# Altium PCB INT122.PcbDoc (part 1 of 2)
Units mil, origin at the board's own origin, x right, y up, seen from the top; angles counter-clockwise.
Board outline 4500 x 3260 mil, 4 copper layers (Top Layer, GND Layer, VCC Layer, Bottom Layer), stack 61.6 mil thick; 94 components, 30 nets, 233 pads, 39 vias.
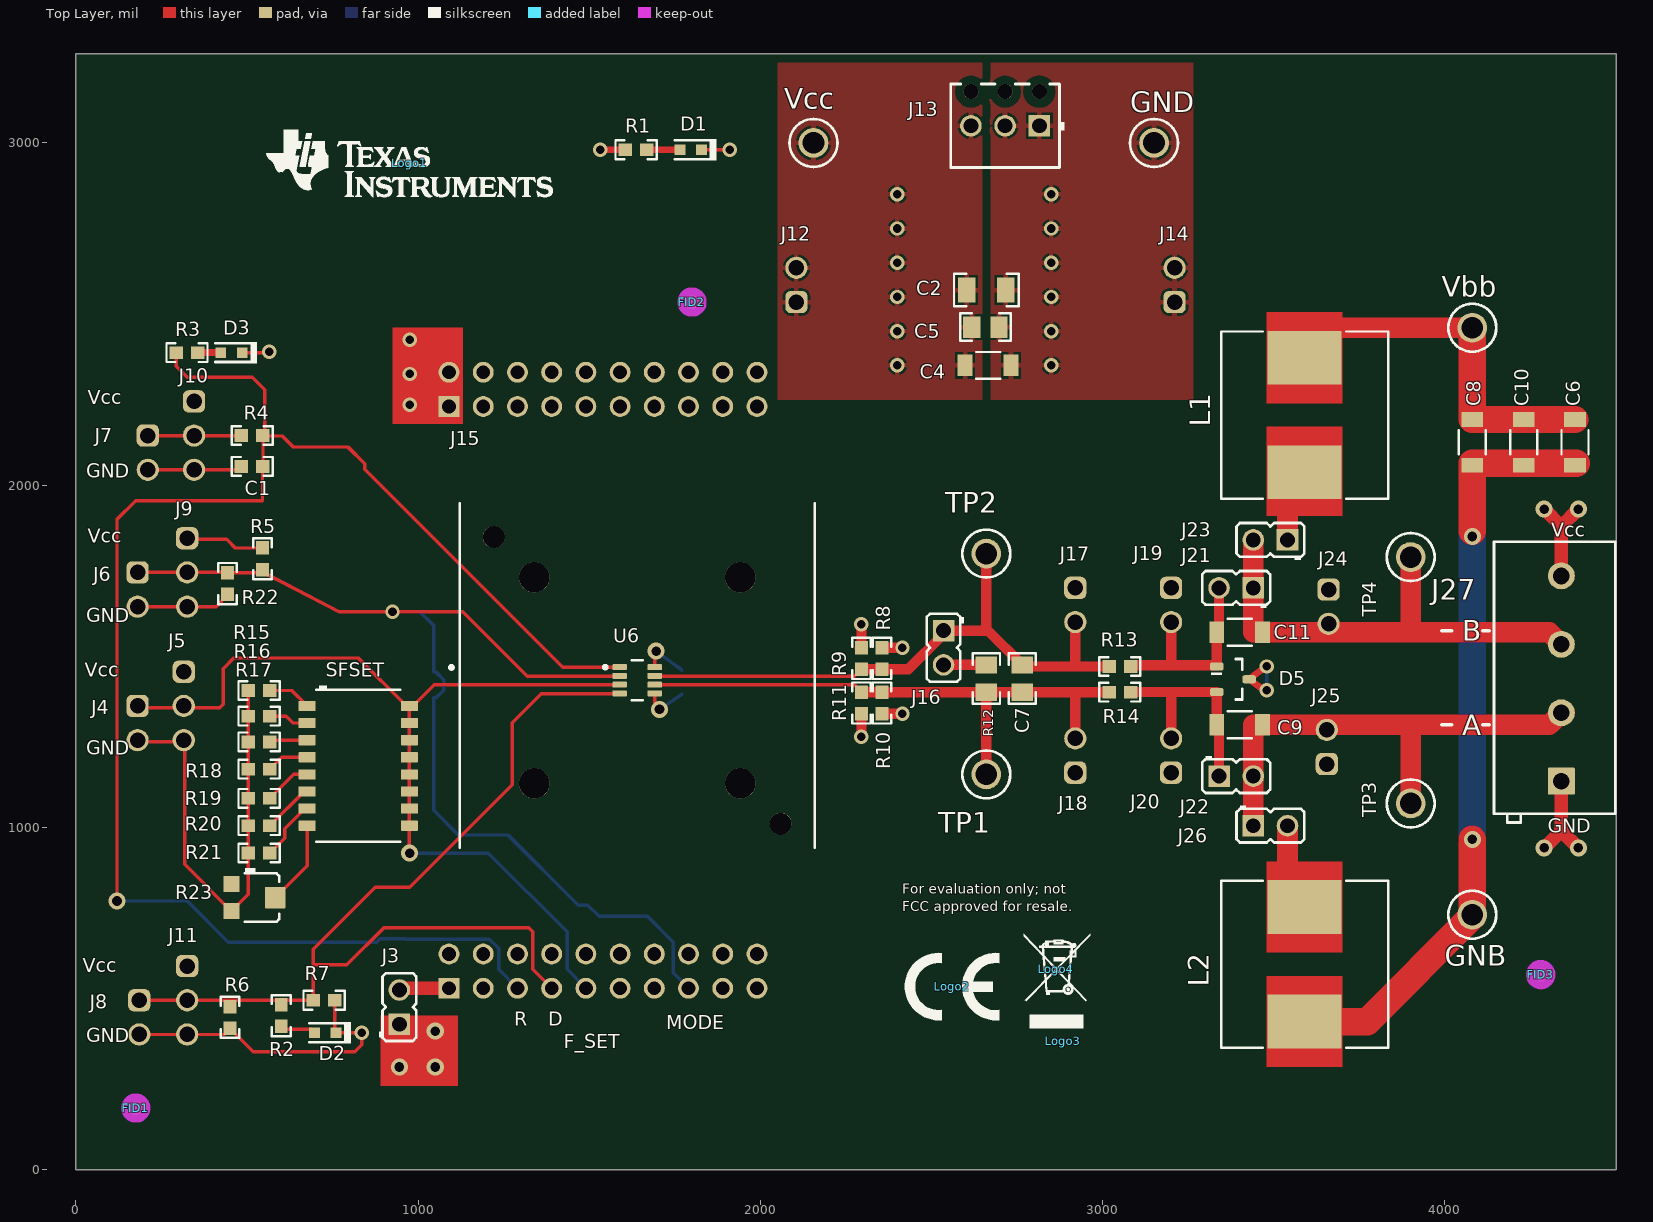
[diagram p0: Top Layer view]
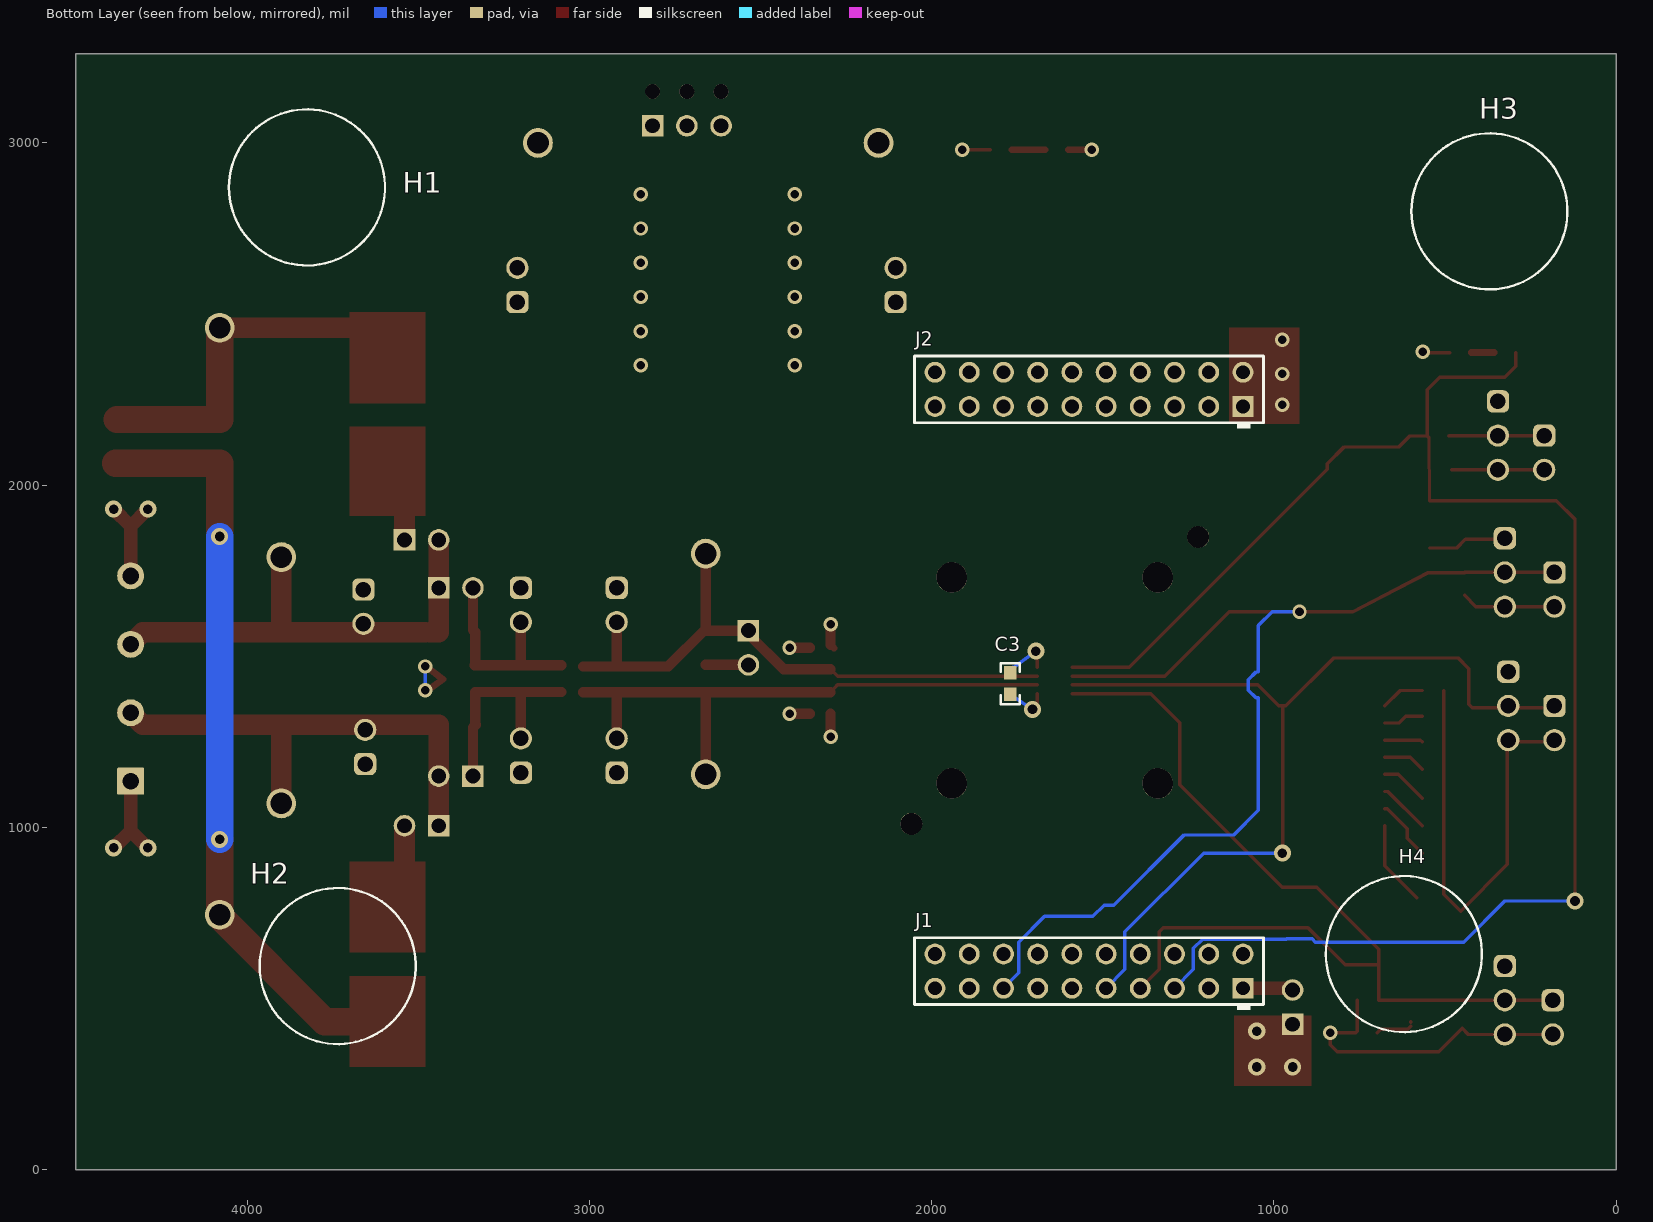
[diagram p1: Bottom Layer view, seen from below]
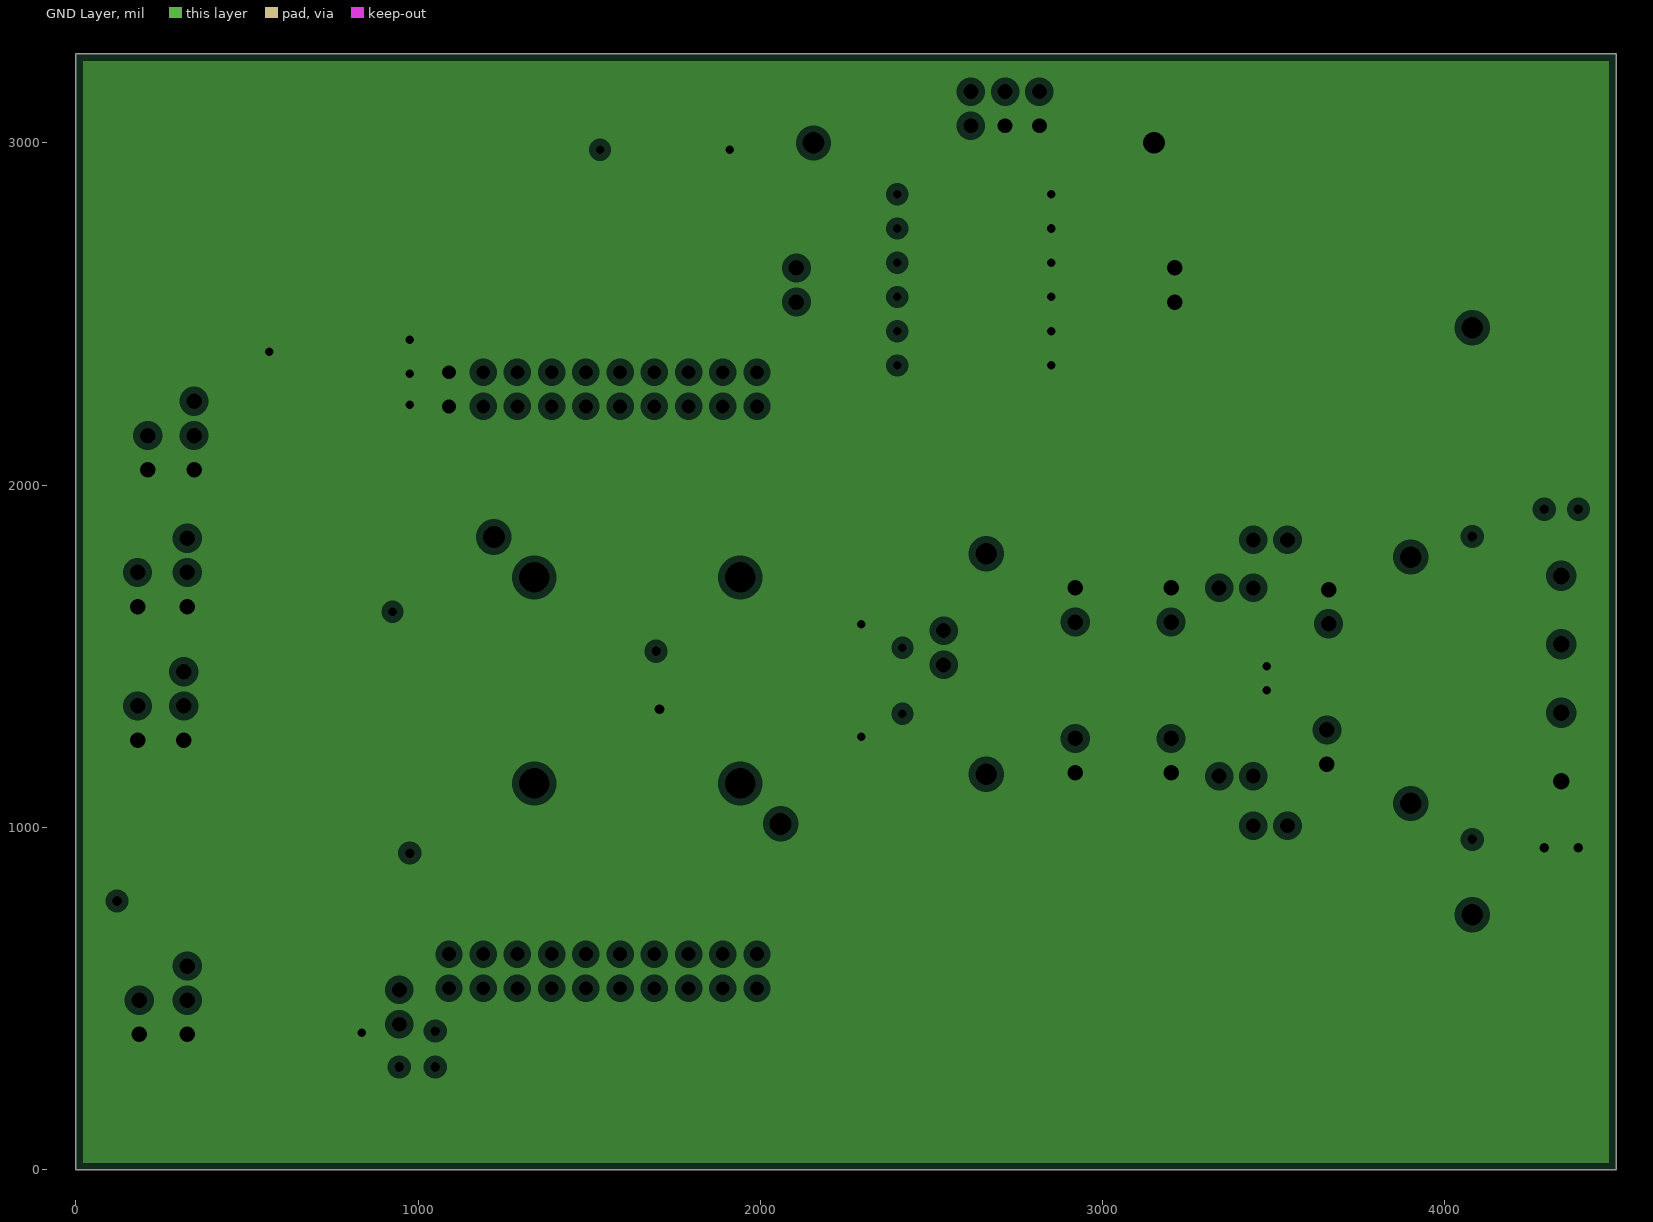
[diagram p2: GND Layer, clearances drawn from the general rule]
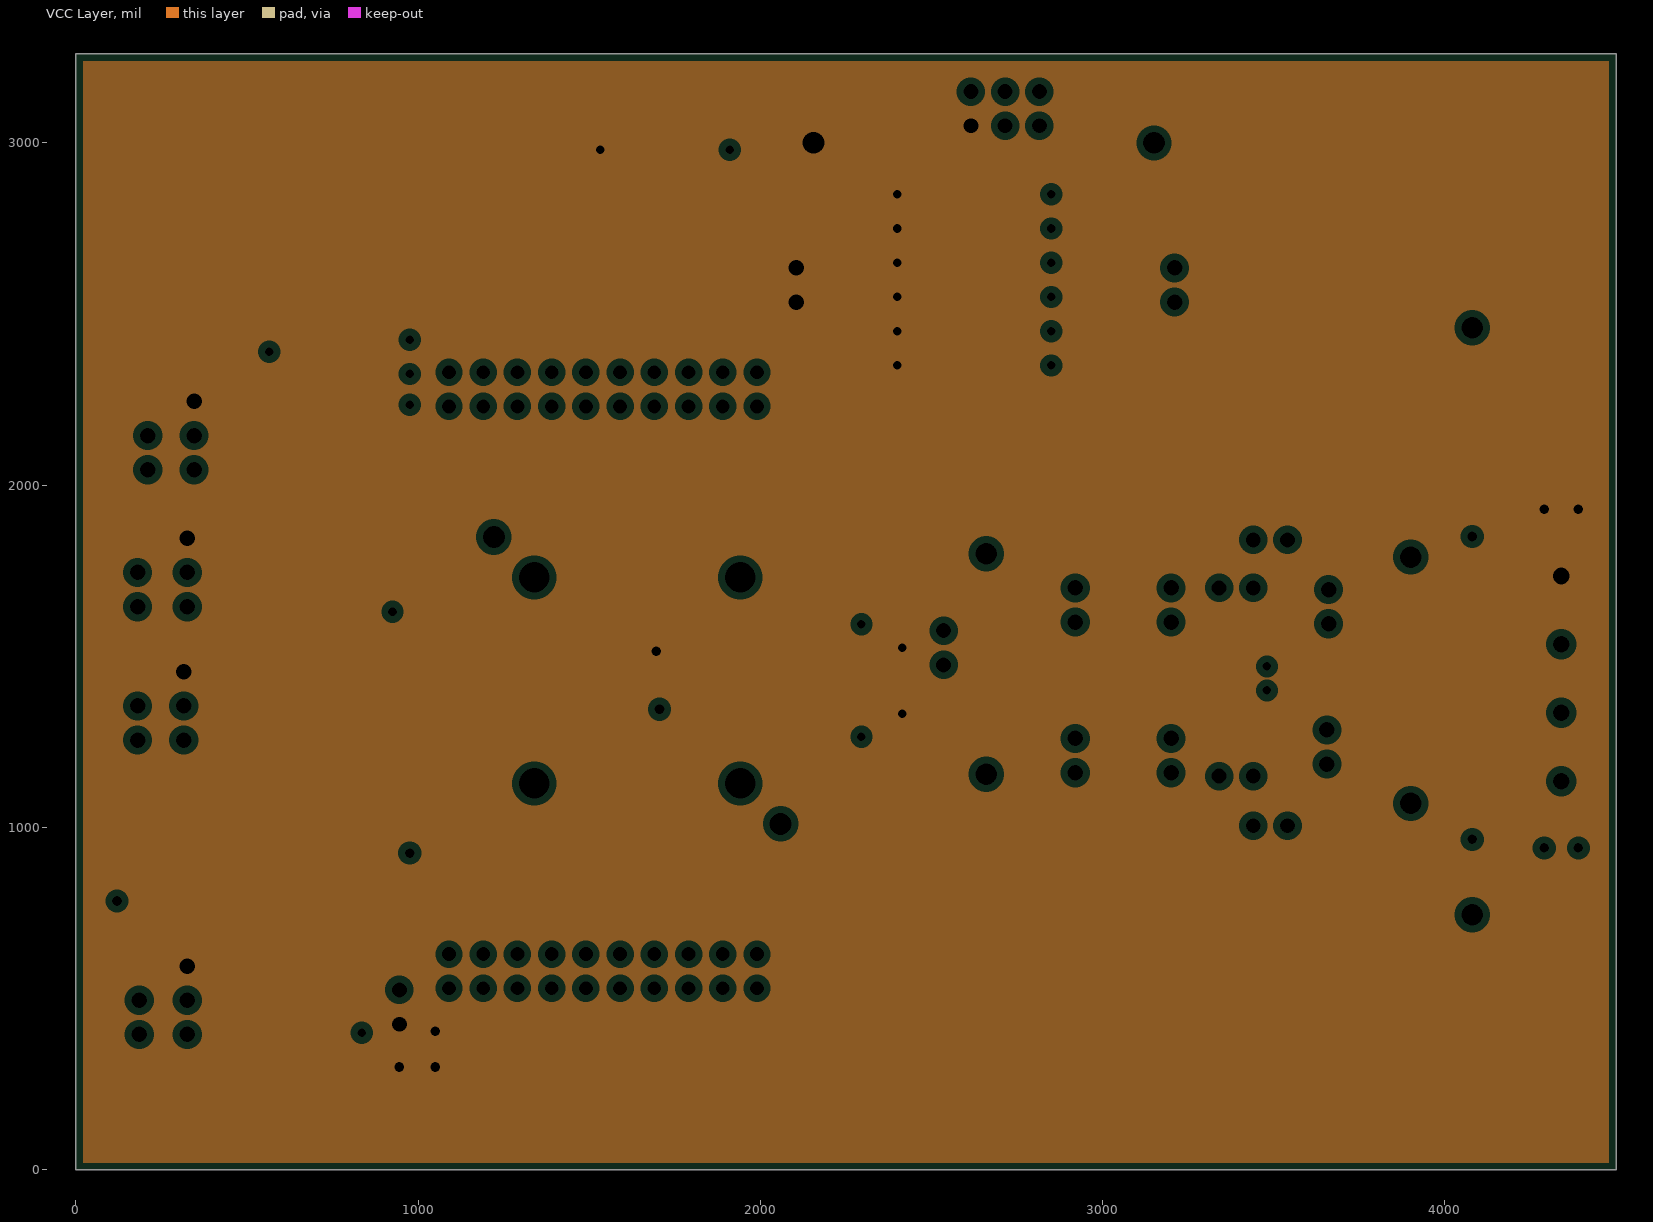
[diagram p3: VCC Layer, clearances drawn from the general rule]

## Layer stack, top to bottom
Top Solder: solder mask 0.4, Solder Resist, Dk 3.5
Top Layer: signal copper 1.4
Dielectric 1: prepreg 8, FR-4, Dk 4.2
GND Layer: plane copper 1.4, net GND_BRD
Dielectric 2: core 40, FR-4, Dk 4.2
VCC Layer: plane copper 1.4, net VCC_BRD
Dielectric 3: prepreg 8, FR-4, Dk 4.2
Bottom Layer: signal copper 1.4
Bottom Solder: solder mask 0.4, Solder Resist, Dk 3.5

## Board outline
0,0 4500,0 4500,3260 0,3260

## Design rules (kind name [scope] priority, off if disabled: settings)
AcuteAngle [All] p1: minimum=4.50000000000000E+0001 checktracksonly=FALSE
AssemblyTestPointUsage [All] p1: valid=2
BoardOutlineClearance BoardOutlineClearance_MountingHoles [OnCopper and InComponentClass('Mounting Holes')] p1: gap=40 ignorepadtopadclearanceinfootprint=FALSE
BoardOutlineClearance BoardOutlineClearance_Poly [OnCopper and IsPoly] p2: gap=25 ignorepadtopadclearanceinfootprint=FALSE
BoardOutlineClearance [OnCopper and Not InComponentClass('Logo') and not InComponentClass('FiducialMark') and not InRegion(1000,500,4000,800) and not InPoly] p3: gap=75 ignorepadtopadclearanceinfootprint=FALSE
Clearance Clearance_Keepouts [((IsTrack Or IsArc) And Not InPoly) And IsFree and IsKeepOut vs ((IsTrack Or IsArc) And Not InPoly) And IsFree and IsKeepOut] p1: gap=0 ignorepadtopadclearanceinfootprint=FALSE
Clearance Clearance_Poly [InPolygon] p2: gap=25 ignorepadtopadclearanceinfootprint=FALSE except(0: Arc-Hole Track-Hole SMDPad-Hole THPad-Hole Via-Hole Fill-Hole Poly-Hole Region-Hole Text-Hole)
Clearance Clearance_FiducialMark [IsKeepOut and InComponentClass('FiducialMark') vs IsPad and InComponentClass('FiducialMark')] p3: gap=0 ignorepadtopadclearanceinfootprint=FALSE
Clearance [All] p4: gap=7.87 ignorepadtopadclearanceinfootprint=FALSE except(0: Arc-Hole Track-Hole SMDPad-Hole THPad-Hole Via-Hole Fill-Hole Poly-Hole Region-Hole Text-Hole)
ComponentClearance ComponentClearance_THtoSMT_Socket [InComponent('JS') vs InComponent('U6')] p1: gap=0 collisioncheckmode=3 verticalgap=0 showdistances=FALSE
ComponentClearance ComponentClearance_L1_Multipad [InComponent('L1') vs InComponent('L1B')] p2: gap=-1 collisioncheckmode=3 verticalgap=100000 showdistances=FALSE
ComponentClearance ComponentClearance_L2_Multipad [InComponent('L2') vs InComponent('L2B')] p3: gap=-1 collisioncheckmode=3 verticalgap=100000 showdistances=FALSE
ComponentClearance ComponentClearance_C13_Multipad [InComponent('C13') vs InComponent('C13B')] p4: gap=-1 collisioncheckmode=3 verticalgap=100000 showdistances=FALSE
ComponentClearance ComponentClearance_C14_Multipad [InComponent('C14') vs InComponent('C14B')] p5: gap=-1 collisioncheckmode=3 verticalgap=100000 showdistances=FALSE
ComponentClearance ComponentClearance_MountingHoles_FiducialMarks [InComponentClass('Mounting Holes') vs InComponentClass('FiducialMark')] p6: gap=50 collisioncheckmode=3 verticalgap=10 showdistances=FALSE
ComponentClearance ComponentClearance_Shunt [InComponentClass('Header') vs InComponentClass('Shunt')] p7: gap=0 collisioncheckmode=3 verticalgap=0 showdistances=FALSE
ComponentClearance ComponentClearance_Logo [InComponentClass('Logo')] p8: gap=30 collisioncheckmode=3 verticalgap=10 showdistances=FALSE
ComponentClearance ComponentClearance_ScrewToNut [(HasFootprint('NY PMS 440 0025 PH')) vs (HasFootprint('Keystone_1902C'))] p9: gap=5 collisioncheckmode=3 verticalgap=10 showdistances=FALSE
ComponentClearance ComponentClearance_MountingHoles [InComponentClass('Mounting Holes')] p10: gap=250 collisioncheckmode=3 verticalgap=100000 showdistances=FALSE
ComponentClearance ComponentClearance_SmallPassives [HasFootprint('0201*') or HasFootprint('0402*') or HasFootprint('0508') or HasFootprint('0603*') or HasFootprint('0612') or HasFootprint('0805*') or HasFootprint('0815*') or HasFootprint('0830*') or HasFootprint('1206*') or HasFootprint('1210*') or HasFootprint('1808*') or HasFootprint('1812*') or HasFootprint('1825*') or HasFootprint('2010*') or HasFootprint('2220*') or HasFootprint('2225*') or HasFootprint('2512*') or HasFootprint('2728*') or HasFootprint('3518*') vs HasFootprint('0201*') or HasFootprint('0402*') or HasFootprint('0508') or HasFootprint('0603*') or HasFootprint('0612') or HasFootprint('0805*') or HasFootprint('0815*') or HasFootprint('0830*') or HasFootprint('1206*') or HasFootprint('1210*') or HasFootprint('1808*') or HasFootprint('1812*') or HasFootprint('1825*') or HasFootprint('2010*') or HasFootprint('2220*') or HasFootprint('2225*') or HasFootprint('2512*') or HasFootprint('2728*') or HasFootprint('3518*')] p11: gap=14.96 collisioncheckmode=3 verticalgap=10 showdistances=FALSE
ComponentClearance ComponentClearance_THtoSMT [IsThruComponent vs IsSMTComponent] p12: gap=40 collisioncheckmode=3 verticalgap=30 showdistances=FALSE
ComponentClearance ComponentClearance_THtoTH [IsThruComponent vs IsThruComponent] p13: gap=30 collisioncheckmode=3 verticalgap=30 showdistances=FALSE
ComponentClearance [All] p14: gap=30 collisioncheckmode=3 verticalgap=10 showdistances=FALSE
DiffPairsRouting [All] p1: maxlimit=100 minlimit=10 mostfreqgap=10 toplayer_minwidth=15 toplayer_maxwidth=15 toplayer_prefwidth=15 bottomlayer_minwidth=15 bottomlayer_maxwidth=15 bottomlayer_prefwidth=15 maxuncoupledlength=1000
FabricationTestPointUsage TestPointUsage [All] p1: valid=2 allowmultiple=FALSE
FabricationTestpoint Testpoint [All] p1: side=3 testpointundercomponent=TRUE minsize=40 maxsize=100 preferedsize=60 minholesize=0 maxholesize=40 preferedholesize=32 testpointgrid=1 allowsidetop=TRUE allowsidebottom=TRUE usegrid=TRUE gridtolerance=0.01
FanoutControl Fanout_LCC [IsLCC] p1: bgadir=Out bgaviamode=Centered fanoutstyle=Auto fanoutdirection=Alternating viagrid=1 // Fanout_LCC (Default Rule)
FanoutControl Fanout_BGA [IsBGA] p2: bgadir=Out bgaviamode=Centered fanoutstyle=Auto fanoutdirection=Alternating viagrid=1 // Fanout_BGA (Default Rule)
FanoutControl Fanout_Default [All] p4: bgadir=Out bgaviamode=Centered fanoutstyle=Auto fanoutdirection=Alternating viagrid=1 // Fanout_Default (Default Rule)
FanoutControl Fanout_Small [(CompPinCount < 5)] p5: bgadir=Out bgaviamode=Centered fanoutstyle=Auto fanoutdirection=OutThenIn viagrid=1 // Fanout_Small (Default Rule)
HoleSize [All] p1: absolutevalues=TRUE maxlimit=251 minlimit=7.87 maxpercent=80.000 minpercent=20.000
MinimumAnnularRing MinimumAnnularRing_ThermalPadVias [IsVia and InAnyComponent] p1: minimumring=5.91
MinimumAnnularRing [All] p2: minimumring=8
MinimumSolderMaskSliver MinimumSolderMaskSliver_Logo [InComponentClass('Logo') vs InComponentClass('Logo')] p1: minsoldermaskwidth=0.7
MinimumSolderMaskSliver [All] p2: minsoldermaskwidth=3.94
PlaneClearance [All] p1: clearance=20
PlaneConnect [All] p1: planeconnectstyle=Relief reliefexpansion=10 reliefentries=4 reliefconductorwidth=10 reliefairgap=10
PolygonConnect [All] p1: connectstyle=Relief reliefconductorwidth=15 reliefentries=4 polygonreliefangle="90 Angle" airgapwidth=7
RoutingVias ThermalPadVias [IsVia and InAnyComponent] p1: holewidth=7.87 width=19.68 viastyle="Through Hole" minholewidth=7.87 minwidth=19.68 maxholewidth=12.99 maxwidth=23.62
RoutingVias [All] p2: holewidth=25 width=42 viastyle="Through Hole" minholewidth=7.87 minwidth=26 maxholewidth=40 maxwidth=65
SilkToBoardRegionClearance [Not ((IsComment or IsDesignator) And (Hide <> 'False')) and not InRegion(1000,500,4000,800)] p1:
SilkToSilkClearance SilkToSilkClearance_Pb-FreeLogo [(HasFootprint('Pb-Free_Overlay_Medium') OR HasFootprint('Pb-Free_Overlay_Small')) vs (HasFootprint('Pb-Free_Overlay_Medium') OR HasFootprint('Pb-Free_Overlay_Small'))] p1: silktosilkclearance=0
SilkToSilkClearance [All] p2: silktosilkclearance=4
SilkToSolderMaskClearance SilkToComponentPadClearance [(IsPad or IsFill or IsRegion) and InAnycomponent] p1: minsilkscreentomaskgap=5 clearancetoexposedcopper=TRUE
SilkToSolderMaskClearance "Silk to Solder Mask Opening" [All] p2: minsilkscreentomaskgap=4 clearancetoexposedcopper=FALSE
SolderMaskExpansion [All] p1: expansion=1.97
Width [All] p1: maxlimit=100 minlimit=6 preferedwidth=10 checkconnectedcopper=TRUE
14 further rules are at their usual default settings.

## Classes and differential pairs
component class Logo: Logo1
component class EVM_Hardware: FID1 FID2 FID3 H1 H2 H3 H4 Logo1 Logo2 Logo3 Logo4 SH-J1 SH-J2 ZZ1 ZZ2 ZZ3 ZZ4
component class FiducialMark: FID1 FID2 FID3
component class AssemblyNote: ZZ1 ZZ2 ZZ3 ZZ4
component class Header: J3 J4 J5 J6 J7 J8 J9 J10 J11 J12 J14 J16 J17 J18 J19 J20 J21 J22 J23 J24 J25 J26 JD1 JF1 JM1 JR1 TL_A tn

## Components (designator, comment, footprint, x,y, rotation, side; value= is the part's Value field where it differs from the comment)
C1 "06035A150JAT2A" 0603 515,2055 r180 top value=15pF
C2 "12063C105KAT2A" 1206 2660,2570 r0 top value=1uF
C3 "C0603C104K9PAC7867" 0603 1770,1420 r90 bottom value=0.1uF
C4 "C3216X7R1V106K160AC" 1206_180 2665,2350 r0 top value=10uF
C5 "GRM21BR61A476ME15L" 0805_HV 2657.5,2461.85 r180 top value=47uF
C6 "C3216X5R1E476M160AC" 1206_190 4380,2125 r90 top value=47uF
C7 "08053C104KAT2A" 0805_HV 2765,1435 r270 top value=0.1uF
C8 "CGA5L2X7R2A105K160AA" 1206_180 4080,2125 r90 top value=1uF
C9 "CGA5L2X7R2A105K160AA" 1206_180 3400.25,1300.3 r180 top value=1uF
C10 "CL31B106KBHNNNE" 1206_180 4230,2125 r90 top value=10uF
C11 "CGA5L2X7R2A105K160AA" 1206_180 3400.25,1570.3 r180 top value=1uF
D1 "150060BS75000" WL-SMCW_Blue 1796.5,2980 r180 top value=Blue
D2 "150060GS75000" WL-SMCW_GREEN 728.7,400 r180 top value=Green
D3 "150060RS75000" WL-SMCW_RED 454.45,2387.2 r180 top value=Red
D5 "CDSOT23-T12C" SOT-23 3380.56,1432.86 r0 top value=12V
FID1 "Fiducial" Fiducial10-20 175,180 r0 top
FID2 "Fiducial" Fiducial10-20 1800,2535 r0 top
FID3 "Fiducial" Fiducial10-20 4280,570 r90 top
GNB "5011" Keystone5011 4080,745 r0 top
GND "5011" Keystone5011 3150,3000 r180 top
H1 "SJ-5303 (CLEAR)" Bumpon_SJ5003Transparent 3825,2870 r90 bottom
H2 "SJ-5303 (CLEAR)" Bumpon_SJ5003Transparent 3735,595 r90 bottom
H3 "SJ-5303 (CLEAR)" Bumpon_SJ5003Transparent 370,2800 r90 bottom
H4 "SJ-5303 (CLEAR)" Bumpon_SJ5003Transparent 620,630 r180 bottom
J1 "SSQ-110-23-F-D" Samtec_SSQ-110-23-F-D 1540,580 r0 bottom
J2 "SSQ-110-23-F-D" Samtec_SSQ-110-23-F-D 1540,2280 r0 bottom
J3 "961102-6404-AR" 3M_961102-6404-AR 945,475 r90 top
J4 "61300211121" WURTH_61300211121 180,1305 r270 top
J5 "61300311121" WURTH_61300311121 315,1355 r270 top
J6 "61300211121" WURTH_61300211121 180,1695 r270 top
J7 "61300211121" WURTH_61300211121 210,2095 r270 top
J8 "61300211121" WURTH_61300211121 185,445 r270 top
J9 "61300311121" WURTH_61300311121 325,1745 r270 top
J10 "61300311121" WURTH_61300311121 345,2145 r270 top
J11 "61300311121" WURTH_61300311121 325,495 r270 top
J12 "61300211121" WURTH_61300211121 2105,2585 r90 top
J13 "1725669" Phoenix_1725669 2715,3050 r180 top
J14 "61300211121" WURTH_61300211121 3210,2585 r90 top
J15 "SK02-0008SOP-GS-04A" FP-SK02-0008SOP-GS-04A_SOCKET-MFG 1640,1415 r0 top
J16 "961102-6404-AR" 3M_961102-6404-AR 2535,1525 r270 top
J17 "61300211121" WURTH_61300211121 2920,1650 r270 top
J18 "61300211121" WURTH_61300211121 2920,1210 r90 top
J19 "61300211121" WURTH_61300211121 3200,1650 r270 top
J20 "61300211121" WURTH_61300211121 3200,1210 r90 top
J21 "961102-6404-AR" 3M_961102-6404-AR 3390,1700 r180 top
J22 "961102-6404-AR" 3M_961102-6404-AR 3390,1150 r0 top
J23 "961102-6404-AR" 3M_961102-6404-AR 3490,1840 r180 top
J24 "61300211121" WURTH_61300211121 3660,1645 r270 top
J25 "61300211121" WURTH_61300211121 3655,1235 r90 top
J26 "961102-6404-AR" 3M_961102-6404-AR 3490,1005 r0 top
J27 "ED120/4DS" On-Shore_ED120_4DS 4340,1435 r90 top
L1 "MSS1278T-124KLB" MSS1278T 3590,2205 r270 top value=120uH
L2 "MSS1278T-124KLB" MSS1278T 3590,600 r270 top value=120uH
Logo1 "Texas Instruments" TI_Stacked_Overlay_Small 975,2940 r0 top
Logo2 "CE Mark" CE_Mark_5mm 2560,535 r0 top
Logo3 "FCC disclaimer" FCC_disclaimer 2885,375 r270 top
Logo4 "WEEE logo" WEEE_Minimum 2865,585 r0 top
R1 "CRCW06031K00JNEA" 0603 1636.5,2980 r0 top value=1.0k
R2 "CRCW06031K00JNEA" 0603 599.8,450 r270 top value=1.0k
R3 "CRCW06031K00JNEA" 0603 324.45,2387.2 r0 top value=1.0k
R4 "RCS06030000Z0EA" 0603 515,2145 r0 top value=0
R5 "RC1608J103CS" 0603 545,1785 r90 top value=10k
R6 "RCP0603W50R0GEB" 0603 450,445 r90 top value=50
R7 "RC1608J103CS" 0603 725,495 r180 top value=10k
R8 "RC0603JR-0715KL" 0603 2355,1493.7 r90 top value=15k
R9 "RC0603FR-0712K4L" 0603 2295,1493.7 r270 top value=12.4k
R10 "RC0603FR-0712K4L" 0603 2355,1363.5 r270 top value=12.4k
R11 "RC0603JR-0715KL" 0603 2295,1363.5 r90 top value=15k
R12 "ERJ-P06J121V" 0805_HV 2660,1435 r90 top value=120
R13 "RCS06030000Z0EA" 0603 3050,1470.26 r0 top value=0
R14 "RCS06030000Z0EA" 0603 3050,1395 r0 top value=0
R15 "ERJ-3EKF1501V" 0603 535,1400 r0 top value=1.50k
R16 "CRCW06034K42FKEA" 0603 535,1325 r0 top value=4.42k
R17 "CRCW06039K31FKEA" 0603 535,1250 r0 top value=9.31k
R18 "RC0603FR-0712K4L" 0603 535,1170 r0 top value=12.4k
R19 "RC0603FR-0719K1L" 0603 535,1085 r0 top value=19.1k
R20 "RC0603FR-0749K9L" 0603 535,1005 r0 top value=49.9k
R21 "CRCW060376K8FKEA" 0603 535,925 r0 top value=76.8k
R22 "RCP0603W50R0GEB" 0603 442.5,1712.5 r90 top value=50
R23 "TC33X-2-103E" Bourns_TC33X-2 525,795 r0 top
SFSET "1-1571983-1" SW_1-1571983-1 825,1180 r0 top
SH-J1 "M7582-05" Harwin_M7582-05 4898,161 r90 top
SH-J2 "M7582-05" Harwin_M7582-05 4648,161 r90 top
TP1 "5012" Keystone5012 2660,1155 r0 top
TP2 "5012" Keystone5012 2660,1800 r0 top
TP3 "5012" Keystone5012 3900,1070 r0 top
TP4 "5012" Keystone5012 3900,1790 r0 top
U6 "THVD8000DDF" DDF0008A-MFG 1640,1430 r0 top
Vbb "5010" Keystone5010 4080,2460 r0 top
Vcc "5010" Keystone5010 2155,3000 r180 top
ZZ1 "This Assembly Note is for PCB labels only" AssemblyNoteLabel 185,3938 r0 top
ZZ2 "These assemblies are ESD sensitive, ESD precautions shall be observed." AssemblyNote 185,3829.11 r0 top
ZZ3 "These assemblies must be clean and free from flux and all contaminants. Use of no clean flux is not acceptable." AssemblyNote 185,3740.56 r0 top
ZZ4 "These assemblies must comply with workmanship standards IPC-A-610 Class 2, unless otherwise specified." AssemblyNote 185,3652 r0 top

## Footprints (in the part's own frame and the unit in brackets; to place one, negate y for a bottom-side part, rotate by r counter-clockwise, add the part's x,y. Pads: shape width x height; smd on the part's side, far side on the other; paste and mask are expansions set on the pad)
3M_961102-6404-AR [mm] "Header, 2.54mm, 2x1, TH"
  rect 1.6x1.6 hole 1.1: 1(-1.27,0)
  round 1.6 hole 1.1: 2(1.27,0)
  silkscreen extent -2.52,-1.25 2.52,1.5, body extent -2.52,-1.25 2.52,1.25, height 8.5
0603 [mm] "0603 from SM-752 data"
  rect 1x0.95 smd: 1(-0.8,0) 2(0.8,0)
  silkscreen extent -1.52,-0.69 1.52,0.69, body extent -0.87,-0.47 0.87,0.47, height 1
0805_HV [mil] "0805 with 30mil clearance between pads"
  rect 50x63 smd: 1(-40,0) 2(40,0)
  silkscreen extent -74,-40 74,40, body extent -43,-29 43,29, height 57
1206 [mm] "1206 from SM-752 data"
  rect 1.3x1.85 smd: 1(-1.45,0) 2(1.45,0)
  silkscreen extent -2.4,-1.21 2.4,1.21, body extent -1.7,-0.9 1.7,0.9, height 1.35
1206_180 [mm] "1206_180"
  rect 1.1x1.6 smd: 1(-1.7,0) 2(1.7,0)
  silkscreen extent -0.9,-1 0.9,1, body extent -1.75,-0.95 1.75,0.95, height 1.8
1206_190 [mm] "1206_190"
  rect 1.1x1.6 smd: 1(-1.7,0) 2(1.7,0)
  silkscreen extent -0.9,-1 0.9,1, body extent -1.75,-0.95 1.75,0.95, height 1.9
AssemblyNote [mil] "Assembly Note"
AssemblyNoteLabel [mil] "Assembly Note for PCB Labels"
Bourns_TC33X-2 [mm] "SMD, 3-Leads, Body 3.8x3.6mm"
  rrect8% 1.2x1.2 smd: 1(-1.8,1) 3(-1.8,-1)
  rrect7% 1.5x1.6 smd: 2(1.45,0)
  silkscreen extent -0.8,-1.8 1.75,2.2, body extent -1.96,-1.8 2,1.8, height 1.13
Bumpon_SJ5003Transparent [mil] "3M Hemispherical Bumpon transparent"
  round 1 on Mech4: 0(0,0)
  silkscreen extent -228,-228 228,228, body extent -219,-219 219,219, height 197
CE_Mark_5mm [mil] "Minimum text height for CE Mark"
  silkscreen extent -138,-98 138,98
DDF0008A-MFG [mm]
  rrect22% 1.05x0.45 smd paste+0 mask+0: 1(-1.3,0.975) 2(-1.3,0.325) 3(-1.3,-0.325) 4(-1.3,-0.975) 5(1.3,-0.975) 6(1.3,-0.325) 7(1.3,0.325) 8(1.3,0.975)
  silkscreen extent -2.5,-1.48 0.4,1.48, body extent -1.92,-1.73 1.92,1.73, height 0.25
FCC_disclaimer [mil]
Fiducial10-20 [mm]
  round 1 smd mask+0.5: 1(0,0)
  Top Layer keep-out circle w1.178: c0,0 r0.5
FP-SK02-0008SOP-GS-04A_SOCKET-MFG [mil]
  rrect29% 41x14 smd paste-39370.1 mask-39370.1: 1(-51,52.5) 2(-51,26.9) 3(-51,1.3) 4(-51,-24.3) 5(51,-24.3) 6(51,1.3) 7(51,26.9) 8(51,52.5)
  round 64 hole 64 unplated paste-39370.1 mask+0: ""(-419,433.5) ""(419,-404.5)
  round 89 hole 89 unplated paste-39370.1 mask+0: ""(-301,-286.5) ""(-301,315.5) ""(301,-286.5) ""(301,315.5)
  silkscreen extent -548,-474 519,532, body extent -507,-674 507,674, height 10
Harwin_M7582-05 [mil] "Single Operation 2.54mm Pitch Open Top Jumper Socket"
  body extent -98,-47 98,47, height 236
Keystone5010 [mil] "Keystone Multipurpose loops"
  round 87 hole 63: 1(0,0)
  silkscreen extent -70,-70 70,70, body extent -63,-63 63,62, height 319
Keystone5011 [mil] "Keystone Multipurpose loops"
  round 87 hole 63: 1(0,0)
  silkscreen extent -70,-70 70,70, body extent -63,-63 63,62, height 319
Keystone5012 [mil] "Keystone Multipurpose loops"
  round 87 hole 63: 1(0,0)
  silkscreen extent -70,-70 70,70, body extent -63,-63 63,62, height 319
MSS1278T [mm] "Coilcraft recommended land pattern.  Document 598-2 rev 10/20/08"
  rect 4x5.5 smd: 1(-4.25,0) 2(4.25,0)
  silkscreen extent -6.2,-6.2 6.2,6.2, body extent -6.15,-6.15 6.15,6.15, height 8.1
On-Shore_ED120_4DS [mm] "ONSHORE"
  rrect5% 2x2 hole 1.25: 1(-7.62,0)
  round 2 hole 1.25: 2(-2.54,0) 3(2.54,0) 4(7.62,0)
  silkscreen extent -10.68,-4 10.16,5, body extent -10.86,-4 10.16,5, height 13
Phoenix_1725669 [mm] "Terminal Block, 3x1, 2.54 mm, TH"
  rect 1.6x1.6 hole 1.1: 1(-2.54,0)
  round 1.6 hole 1.1: 2(0,0) 3(2.54,0)
  round 1.1 hole 1.1 unplated mask+0: 4(-2.54,-2.54) 5(0,-2.54) 6(2.54,-2.54)
  silkscreen extent -4.4,-3.1 4.04,3.1, body extent -4.04,-3.1 4.04,3.1, height 8.5
Samtec_SSQ-110-23-F-D [mm] "Receptacle, 2.54mm, 10x2, TH"
  rect 1.55x1.55 hole 1.02: 1(-11.43,1.27)
  round 1.55 hole 1.02: 2(-11.43,-1.27) 3(-8.89,1.27) 4(-8.89,-1.27) 5(-6.35,1.27) 6(-6.35,-1.27) 7(-3.81,1.27) 8(-3.81,-1.27) 9(-1.27,1.27) 10(-1.27,-1.27) 11(1.27,1.27) 12(1.27,-1.27) 13(3.81,1.27) 14(3.81,-1.27) 15(6.35,1.27) 16(6.35,-1.27) 17(8.89,1.27) 18(8.89,-1.27) 19(11.43,1.27) 20(11.43,-1.27)
  silkscreen extent -12.95,-2.48 12.95,2.9, body extent -12.95,-2.48 12.95,2.48, height 8.51
SOT-23 [mm] "SOT23, 3-Leads, Body 2.9x1.3mm, Pitch 0.95mm, Lead Span 2.5mm, IPC Medium Density"
  rrect50% 1x0.6 smd: 1(-1.2,0.95) 2(-1.2,-0.95) 3(1.2,0)
  silkscreen extent -1.63,-1.5 0.7,1.5, body extent -1.16,-1.45 1.21,1.45, height 1
SW_1-1571983-1 [mm] "SMD, 16-Leads, Body 11.28x6.2mm"
  rrect13% 1.27x0.76 smd: 1(-3.795,4.445) 2(-3.795,3.175) 3(-3.795,1.905) 4(-3.795,0.635) 5(-3.795,-0.635) 6(-3.795,-1.905) 7(-3.795,-3.175) 8(-3.795,-4.445) 9(3.795,-4.445) 10(3.795,-3.175) 11(3.795,-1.905) 12(3.795,-0.635) 13(3.795,0.635) 14(3.795,1.905) 15(3.795,3.175) 16(3.795,4.445)
  silkscreen extent -3.1,-5.64 3.1,5.95, body extent -4.06,-5.64 4.06,5.64, height 2.28
TI_Stacked_Overlay_Small [mil]
  silkscreen extent -418,-98 418,98
WEEE_Minimum [mil] "WEEElie bin"
  silkscreen extent -95,-172 99,104
WL-SMCW_Blue [mm] "SMD, 2-Leads, Body 1.6x0.8mm"
  rect 0.8x0.8 smd: 1(-0.8,0) 2(0.8,0)
  silkscreen extent -1.9,-0.8 1.2,0.8, body extent -0.85,-0.45 0.85,0.45, height 0.8
WL-SMCW_GREEN [mm] "WURTH"
  rect 0.8x0.8 smd: 1(-0.8,0) 2(0.8,0)
  silkscreen extent -1.9,-0.8 1.2,0.8, body extent -0.85,-0.45 0.85,0.45, height 0.8
WL-SMCW_RED [mm] "WURTH"
  rect 0.8x0.8 smd: 1(-0.8,0) 2(0.8,0)
  silkscreen extent -1.9,-0.8 1.2,0.8, body extent -0.85,-0.45 0.85,0.45, height 0.8
WURTH_61300211121 [mm] "Header, 2.54mm, 2x1, TH"
  rrect50% 1.65x1.65 hole 1.15: 1(-1.27,0)
  round 1.65 hole 1.15: 2(1.27,0)
  body extent -2.54,-1.27 2.54,1.27, height 8.54
WURTH_61300311121 [mm] "Header, 2.54mm, 3x1, TH"
  rrect50% 1.65x1.65 hole 1.15: 1(-2.54,0)
  round 1.65 hole 1.15: 2(0,0) 3(2.54,0)
  body extent -3.81,-1.27 3.81,1.27, height 8.54

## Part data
C1: library part CMP-0006767-4, "CAP, CERM, 15 pF, 50 V, +/- 5%, C0G/NP0, 0603", Cap_Case=0603, Manufacturer=AVX, Supplier Part Number 1=478-1165-1-ND, TempCo=C0G/NP0, Tolerance_%=5%, Value1="0.32 ohm", Value2=50V, ValueDisplayed=15pF
C2: library part CMP-0008509-2, "CAP, CERM, 1 uF, 25 V, +/- 10%, X7R, 1206", Cap_Case=1206, Manufacturer=AVX, Supplier Part Number 1=478-1567-1-ND, TempCo=X7R, Tolerance_%=10%, Value1="0.013 ohm", Value2=25V, ValueDisplayed=1uF
C3: library part CMP-0085846-1, "CAP, CERM, 0.1 µF, 6.3 V,+/- 10%, X5R, 0603", Cap_Case=0603, Manufacturer=Kemet, TempCo=X5R, Tolerance_%=10%, Value2=6.3V, ValueDisplayed=0.1µF
C4: library part CMP-0008705-2, "CAP, CERM, 10 uF, 35 V, +/- 10%, X7R, 1206", Cap_Case=1206_180, Manufacturer=TDK, Supplier Part Number 1=445-14799-1-ND, TempCo=X7R, Tolerance_%=10%, Value1="0.002229 ohm", Value2=35V, ValueDisplayed=10uF
C5: library part CMP-0078699-1, "CAP, CERM, 47 µF, 10 V,+/- 20%, X5R, 0805", Cap_Case=0805, Manufacturer=MuRata, Supplier Part Number 1=490-9961-1-ND, TempCo=X5R, Tolerance_%=20%, Value2=10V, ValueDisplayed=47µF
C6: library part CMP-0008656-2, "CAP, CERM, 47 uF, 25 V, +/- 20%, X5R, 1206_190", Cap_Case=1206, Manufacturer=TDK, Supplier Part Number 1=445-8047-1-ND, TempCo=X5R, Tolerance_%=20%, Value1=Unknown, Value2=25V, ValueDisplayed=47uF
C7: library part CMP-0007567-2, "CAP, CERM, 0.1 uF, 25 V, +/- 10%, X7R, 0805", Cap_Case=0805, Manufacturer=AVX, Supplier Part Number 1=478-3755-1-ND, TempCo=X7R, Tolerance_%=10%, Value1="0.28 ohm", Value2=25V, ValueDisplayed=0.1uF
C8 C9 C11: library part CMP-0008779-2, "CAP, CERM, 1 uF, 100 V, +/- 10%, X7R, AEC-Q200 Grade 1, 1206", Cap_Case=1206_180, Manufacturer=TDK, Supplier Part Number 1=445-5845-1-ND, TempCo=X7R, Tolerance_%=10%, Value1="0.004575 ohm", Value2=100V, ValueDisplayed=1uF
C10: library part CMP-0008802-2, "CAP, CERM, 10 uF, 50 V, +/- 10%, X7R, 1206", Cap_Case=1206, Manufacturer=Samsung, Supplier Part Number 1=1276-6767-1-ND, TempCo=X7R, Tolerance_%=10%, Value1=Unknown, Value2=50V, ValueDisplayed=10uF
D1: library part CMP-0002946-3, "LED, Blue, SMD", Color=Blue, Manufacturer="Wurth Elektronik", Power_TotalModule=105mW, Value1=0.105W, Value2=3.2V
D2: library part CMP-0002905-2, "LED, Green, SMD", Color=Green, Manufacturer="Wurth Elektronik", Value1=W, Value2=3.2V
D3: library part CMP-0002947-3, "LED, Red, SMD", Color=Red, Manufacturer="Wurth Elektronik", Power_TotalModule=72mW, Value1=0.072W, Value2=2V
D5: library part CMP-0005918-3, "Diode, TVS, Bi, 12 V, 25.9 Vc, SOT-23", Manufacturer=Bourns, Value1=500W
FID1 FID2 FID3: library part CMP-0077181-1, "Fiducial mark.  There is nothing to buy or mount.", Manufacturer=N/A
GNB GND: library part CMP-0055148-1, "Test Point, Multipurpose, Black, TH", Color=Black, Manufacturer=Keystone, Supplier Part Number 1=36-5011-ND
H1 H2 H3 H4: library part CMP-0003620-1, "Bumpon, Hemisphere, 0.44 X 0.20, Clear", Manufacturer=3M, Supplier Part Number 1=SJ5303-7-ND
J1 J2: library part CMP-0055675-1, "Receptacle, 2.54mm, 10x2, Gold, TH", Color=Black, Current_A=6.3A, Manufacturer=Samtec, Voltage_V=550V
J3 J16 J21 J22 J23 J26: library part CMP-0075197-1, "Header, 2.54mm, 2x1, TH", Color=Black, Current_A=2A, Manufacturer=3M, Supplier Part Number 1=3M9447-ND, Voltage_V=1kV
J4 J6 J7 J8 J12 J14 J17 J18 J19 J20 J24 J25: library part CMP-0054794-2, "Header, 2.54 mm, 2x1, Gold, TH", Color=Black, Manufacturer="Wurth Elektronik", Supplier Part Number 1=732-5315-ND
J5 J9 J10 J11: library part CMP-0054796-2, "Header, 2.54 mm, 3x1, Gold, TH", Color=Black, Manufacturer="Wurth Elektronik", Supplier Part Number 1=732-5316-ND
J13: library part CMP-0055500-1, "Terminal Block, 3x1, 2.54 mm, TH", Manufacturer="Phoenix Contact", Supplier Part Number 1=277-1274-ND
J15: library part CMP-0088168-1, "CUSTOM SOCKET FOR 1.6X2.9X1.1mm DEVICE, DDF PACKAGE, 0.65mm PITCH, HIGH SPEED SPRING PROBES POGO-1300", DUT-PackageType=SOT23-8, Manufacturer=RST
J27: library part CMP-0074939-1, "Terminal Block, 5.08 mm, 4x1, Brass, TH", Color=Blue, Current_A=15A, Manufacturer="On-Shore Technology", Supplier Part Number 1=ED2227-ND, Voltage_V=300V
L1 L2: library part CMP-0061931-2, "Inductor, Shielded Drum Core, Ferrite, 120 uH, 1.9 A, 0.18 ohm, SMD", Manufacturer=Coilcraft, Value1="0.18 ohm", Value2=1.9A, ValueDisplayed=120uH
Logo1: library part CMP-0074838-1, "Texas Instrument Corporate Signature"
Logo2: library part CMP-0074844-1
Logo3: library part CMP-0074847-1, "FCC_disclaimer"
Logo4: library part CMP-0074769-1
R1 R2 R3: library part CMP-0025729-4, "RES, 1.0 k, 5%, 0.1 W, AEC-Q200 Grade 0, 0603", Manufacturer=Vishay-Dale, Power_W=100mW, Supplier Part Number 1=541-1.0KGCT-ND, TempCo="200 ppm/C", Tolerance_%=5%, Value2=0.1W, Value_Code=1k00, ValueDisplayed=1.0k
R4 R13 R14: library part CMP-0081973-1, "RES, 0, 0%, 0.25 W, AEC-Q200 Grade 0, 0603", Manufacturer=Vishay-Dale, Power_W=250mW, Supplier Part Number 1=541-2779-1-ND, Tolerance_%=0%, Value2=0.25W, Value_Code=0
R5 R7: library part CMP-0025945-3, "RES, 10 k, 5%, 0.1 W, 0603", Manufacturer="Samsung Electro-Mechanics", Power_W=100mW, Supplier Part Number 1=1276-5086-1-ND, TempCo="100 ppm/C", Tolerance_%=5%, Value2=0.1W, Value_Code=10k0, ValueDisplayed=10k
R6 R22: library part CMP-0082504-1, "RES, 50, 2%, 3.9 W, 0603", Manufacturer=Vishay-Dale, Power_W=3.9W, Supplier Part Number 1=541-2655-1-ND, TempCo="150 ppm/C", Tolerance_%=2%, Value_Code=50R0, ValueDisplayed=50
R8 R11: library part CMP-0025890-5, "RES, 15 k, 5%, 0.1 W, 0603", Manufacturer=Yageo, Power_W=100mW, Supplier Part Number 1=311-15KGRCT-ND, TempCo="100 ppm/C", Tolerance_%=5%, Value2=0.1W, Value_Code=15k0, ValueDisplayed=15k
R9 R10 R18: library part CMP-0022777-5, "RES, 12.4 k, 1%, 0.1 W, 0603", Manufacturer=Yageo, Power_W=100mW, Supplier Part Number 1=311-12.4KHRCT-ND, TempCo="100 ppm/C", Tolerance_%=1%, Value2=0.1W, Value_Code=12k4, ValueDisplayed=12.4k
R12: library part CMP-0020795-2, "RES, 120, 5%, 0.5 W, 0805", Manufacturer=Panasonic, Power_W=500mW, Supplier Part Number 1=P120ADCT-ND, TempCo="200 ppm/C", Tolerance_%=5%, Value2=0.5W, Value_Code=120R, ValueDisplayed=120
R15: library part CMP-0022689-3, "RES, 1.50 k, 1%, 0.1 W, 0603", Manufacturer=Panasonic, Power_W=100mW, Supplier Part Number 1=P1.50KHCT-ND, TempCo="100 ppm/C", Tolerance_%=1%, Value2=0.1W, Value_Code=1k50, ValueDisplayed=1.50k
R16: library part CMP-0022453-4, "RES, 4.42 k, 1%, 0.1 W, AEC-Q200 Grade 0, 0603", Manufacturer=Vishay-Dale, Power_W=100mW, Supplier Part Number 1=541-4.42KHCT-ND, TempCo="100 ppm/C", Tolerance_%=1%, Value2=0.1W, Value_Code=4k42, ValueDisplayed=4.42k
R17: library part CMP-0022666-4, "RES, 9.31 k, 1%, 0.1 W, AEC-Q200 Grade 0, 0603", Manufacturer=Vishay-Dale, Power_W=100mW, Supplier Part Number 1=541-9.31KHCT-ND, TempCo="100 ppm/C", Tolerance_%=1%, Value2=0.1W, Value_Code=9k31, ValueDisplayed=9.31k
R19: library part CMP-0022860-5, "RES, 19.1 k, 1%, 0.1 W, 0603", Manufacturer=Yageo, Power_W=100mW, Supplier Part Number 1=311-19.1KHRCT-ND, TempCo="100 ppm/C", Tolerance_%=1%, Value2=0.1W, Value_Code=19k1, ValueDisplayed=19.1k
R20: library part CMP-0023142-5, "RES, 49.9 k, 1%, 0.1 W, 0603", Manufacturer=Yageo, Power_W=100mW, Supplier Part Number 1=311-49.9KHRCT-ND, TempCo="100 ppm/C", Tolerance_%=1%, Value2=0.1W, Value_Code=49k9, ValueDisplayed=49.9k
R21: library part CMP-0022593-4, "RES, 76.8 k, 1%, 0.1 W, AEC-Q200 Grade 0, 0603", Manufacturer=Vishay-Dale, Power_W=100mW, Supplier Part Number 1=541-76.8KHCT-ND, TempCo="100 ppm/C", Tolerance_%=1%, Value2=0.1W, Value_Code=76k8, ValueDisplayed=76.8k
R23: library part CMP-0065392-2, "TRIMMER 10K OHM 0.1W", Manufacturer=Bourns, Supplier Part Number 1=TC33X-103ECT-ND
SFSET: library part CMP-0065297-1, "Switch, 8SPST, 0.025 A, 24 VDC, SMD", CurrentRating_mA=25A, Manufacturer="TE Connectivity", Supplier Part Number 1=450-1761-1-ND
SH-J1 SH-J2: library part CMP-0078738-1, "Single Operation 2.54mm Pitch Open Top Jumper Socket", Manufacturer=Harwin, Supplier Part Number 1=952-2881-ND
TP1 TP2 TP3 TP4: library part CMP-0055149-1, "Test Point, Multipurpose, White, TH", Color=White, Manufacturer=Keystone, Supplier Part Number 1=36-5012-ND
U6: library part CMP-0088703-2, "RS-485 Transceiver with OOK Modulation for Power Line Communication", Manufacturer="Texas Instruments", Max Supply Voltage=5.5V, Min Supply Voltage=3V, Nominal Supply Current=1.3-3.2mA, Operating Temperature Range="-40°C to +150°C"
Vbb Vcc: library part CMP-0055147-1, "Test Point, Multipurpose, Red, TH", Color=Red, Manufacturer=Keystone, Supplier Part Number 1=36-5010-ND
ZZ1: library part CMP-0003616-3
ZZ2: library part CMP-0077236-1
ZZ3: library part CMP-0077237-1
ZZ4: library part CMP-0077238-1

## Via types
v1: diameter 42, hole 25, Top Layer to Bottom Layer, 26 vias
v2: diameter 50, hole 28, Top Layer to Bottom Layer, 13 vias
